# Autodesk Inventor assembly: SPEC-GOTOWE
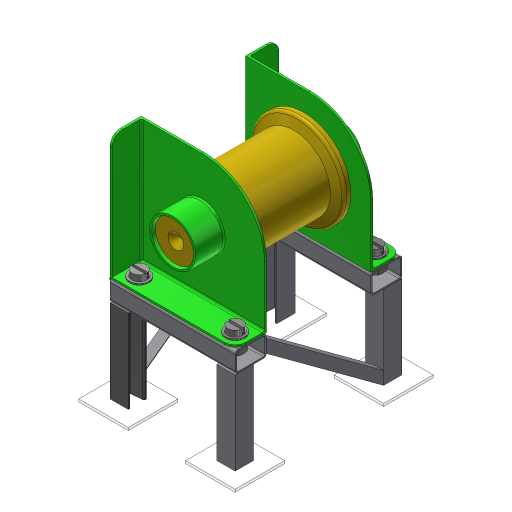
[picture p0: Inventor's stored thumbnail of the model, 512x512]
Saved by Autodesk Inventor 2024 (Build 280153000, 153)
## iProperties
_SolveAssemblyDoc: Frame Generator Solve Assembly
_Version: 25.0.0
Company: ATC
Created: 2023-03
Part Number: SPEC-GOTOWE
Document SubType Name: Assembly
Designer: Andrzej Jaskulski
Checked By: A.J.
Engr Approved By: Andrzej Jaskulski
Mfg Approved By: Andrzej Jaskulski
Authority: A.J.
Title: A.J.: Kurs R2024-MEP
Author: Andrzej Jaskulski
Revision Number: 1/24
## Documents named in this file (10)
- C:\Users\AndJas\Documents\R2024-MEP\Obszar roboczy\SPEC\GOTOWE\SPEC-GOTOWE.iam
- C:\Users\AndJas\Documents\R2024-MEP\Obszar roboczy\SPEC\GOTOWE\RAMA-Szkielet.ipt
- C:\Users\AndJas\Documents\R2024-MEP\Obszar roboczy\SPEC\GOTOWE\Kotwy.ipt
- C:\Users\AndJas\Documents\R2024-MEP\Obszar roboczy\SPEC\GOTOWE\SPEC-GOTOWE\Rama\RAMA.iam
- C:\Users\AndJas\Documents\R2024-MEP\Obszar roboczy\SPEC\GOTOWE\Zespół Rolki-R.iam
- C:\Users\AndJas\Documents\R2024-MEP\Obszar roboczy\SPEC\GOTOWE\SPEC-GOTOWE\Design Accelerator\M20-1.iam
- M20-1.iam
- C:\Users\AndJas\Documents\R2024-MEP\Obszar roboczy\SPEC\GOTOWE\SPEC-GOTOWE\Design Accelerator\M20-2.iam
- C:\Users\AndJas\Documents\R2024-MEP\Obszar roboczy\SPEC\GOTOWE\SPEC-GOTOWE\Design Accelerator\M20-1a.iam
- C:\Users\AndJas\Documents\R2024-MEP\Obszar roboczy\SPEC\GOTOWE\SPEC-GOTOWE\Design Accelerator\M20-2a.iam
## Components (8 placed, 8 different names)
1. Kotwy:1
2. RAMA-Szkielet:1 — Zestawiające:1, Zestawiające:2
3. RAMA:1 [sub-assembly]
4. Zespół Rolki-R:1 [sub-assembly] — Zestawiające:1, Zestawiające:2, Zestawiające:5, Zestawiające:6, Zestawiające:9, Zestawiające:10, Zestawiające:11, Zestawiające:12, Zestawiające:13, Zestawiające:14
5. M20-1:1 [sub-assembly] — Zestawiające:13, Zestawiające:14
6. M20-2:1 [sub-assembly] — Zestawiające:5, Zestawiające:6
7. M20-1a:1 [sub-assembly] — Zestawiające:11, Zestawiające:12
8. M20-2a:1 [sub-assembly] — Zestawiające:9, Zestawiające:10
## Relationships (10: Mate 10)
- Zestawiające:1 [Mate]: RAMA-Szkielet:1 ↔ Zespół Rolki-R:1
- Zestawiające:2 [Mate]: RAMA-Szkielet:1 ↔ Zespół Rolki-R:1
- Zestawiające:5 [Mate]: Zespół Rolki-R:1 ↔ M20-2:1
- Zestawiające:6 [Mate]: Zespół Rolki-R:1 ↔ M20-2:1
- Zestawiające:9 [Mate]: Zespół Rolki-R:1 ↔ M20-2a:1
- Zestawiające:10 [Mate]: Zespół Rolki-R:1 ↔ M20-2a:1
- Zestawiające:11 [Mate]: Zespół Rolki-R:1 ↔ M20-1a:1
- Zestawiające:12 [Mate]: Zespół Rolki-R:1 ↔ M20-1a:1
- Zestawiające:13 [Mate]: Zespół Rolki-R:1 ↔ M20-1:1
- Zestawiające:14 [Mate]: Zespół Rolki-R:1 ↔ M20-1:1
